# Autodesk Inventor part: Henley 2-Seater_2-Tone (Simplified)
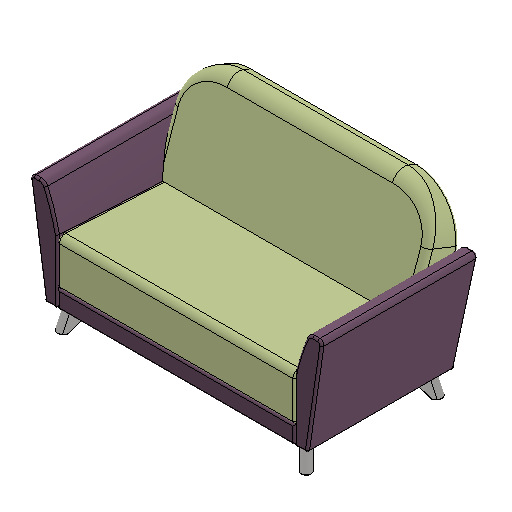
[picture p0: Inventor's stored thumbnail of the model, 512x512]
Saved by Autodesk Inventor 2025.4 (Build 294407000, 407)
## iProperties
Created: 2026-05
Part Number: Henley 2-Seater_2-Tone (Simplified)
Material: Generic
Description: 2-SEATER
Document SubType Name: Modeling
Designer: Brian.Thangei
Density: 1 g/cm^3
Appearance: Default
Project: HENLEY
Sending System: SolidWorks 2026
Preprocessor: SwSTEP 2.0
Title: Henley 2-Seater.STEP
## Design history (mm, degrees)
feature "NONE"
feature "NONE:1"
feature "NONE:2"
feature "NONE:3"
feature "NONE:4"
feature "NONE:5"
feature "NONE:6"
feature "NONE:7"
feature "NONE:8"
workplane "Work Plane1"
workplane "Work Plane2"
workplane "Work Plane3"
workplane "Work Plane4"
workplane "Work Plane5"
workplane "Work Plane6"
node "Direct Edit1"
node "FOOT"
node "ARM"
node "FOOT2"
node "FOOT3"
node "FOOT4"
node "BASE"
node "ARM2"
node "SEAT"
node "BACK"
move_body "Move1" dims "d0" = 10
move_body "Move2" dims "d3" = -10
other parameters: "d1" = 0, "d2" = 0, "d4" = 0, "d5" = 0
